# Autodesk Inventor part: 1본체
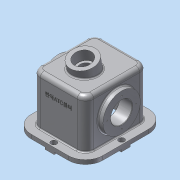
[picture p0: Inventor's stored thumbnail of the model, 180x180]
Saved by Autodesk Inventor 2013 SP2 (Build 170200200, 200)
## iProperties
Created: 2014-11
Part Number: 1본체
Material: 알루미늄 6061
Document SubType Name: Modeling
Designer: dgall
Density: 2.71 g/cm^3
Mass: 2882.15 g
Surface Area: 2079.16 cm^2
Volume: 1063.52 cm^3
Author: dgall
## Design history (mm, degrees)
sketch "스케치1"
  geometry: L1 (-76, 59)-(76, 59); L2 (76, 59)-(76, -59); L3 (76, -59)-(-76, -59); L4 (-76, -59)-(-76, 59); 3 further points
  constraints: 8 end point, 2 midpoint, 2 parallel, 1 horizontal, 1 horizontal alignment, 1 perpendicular, 1 vertical alignment
  dimensions: "d0" = 152 distance of L1.start L1.end; "d2" = 118 distance of L1.end L2.end
extrude "돌출1" new body sketch "스케치1" stored distance "d3" = 130; taper "d4" = 0 deg
feature "쉘1" dims "d5" = 10
sketch "스케치2"
  geometry: L1 (142, -10)-(142, -120) reference; L2 (142, -120)-(10, -120) reference; L3 (10, -120)-(10, -10) reference; L4 (10, -10)-(142, -10) reference; L5 (174, -152)-(-22, -152); L6 (-22, -152)-(-22, 22); L7 (-22, 22)-(174, 22); L8 (174, 22)-(174, -152); 3 further points
  constraints: 8 end point, 2 midpoint, 2 parallel, 1 horizontal, 1 horizontal alignment, 1 perpendicular, 1 vertical alignment
  dimensions: "d6" = 196 distance of L5.start L5.end; "d8" = 174 distance of L5.end L6.end
extrude "돌출2" join sketch "스케치2" distance "d9" = 10; taper "d10" = 0 deg
sketch "스케치3"
  geometry: L1 (152, -128)-(-22, -128) reference; 2 further points
  constraints: 1 vertical alignment, 1 other
  dimensions: "d11" = 92 distance from line of point (65, -36) L1
feature "엠보싱1" sketch "스케치3" dims "d6" = 196, "d8" = 174, "d12" = 1, "d13" = 0
sketch "스케치4"
  geometry: L1 (-66, -69)-(66, -69) reference; C1 r 45.5 at (0, -1); 1 further point
  constraints: 1 centre point, 1 vertical alignment
  dimensions: "d15" = 91 diameter of C1; "d57" = 68 distance from line of C1.centre L1
extrude "돌출3" join sketch "스케치4" distance "d16" = 12; taper "d17" = 0 deg
sketch "스케치5"
  geometry: C1 r 45.5 at (0, 0) reference; 2 further points
  constraints: 1 vertical alignment
  dimensions: "d18" = 35 distance of point (0, 35) C1.centre
hole "구멍1" sketch "스케치5" at (0, 35) diameter "d19" = 3.242; stored, may be unused: countersink angle "d23" = 90 deg, drill point angle "d25" = 118 deg; dims "d20" = 13, "d21" = 4, "d22" = 2, "d24" = 16
sketch "스케치6"
  geometry: L1 (174, -152)-(174, 22) reference; L2 (-22, 22)-(-22, -152) reference; L3 (174, -54)-(154, -54); L4 (154, -54)-(154, -76); L5 (154, -76)-(174, -76); L6 (174, 22)-(-22, 22) reference; L7 (87, 22)-(87, 2); L8 (87, 2)-(65, 2); L9 (65, 2)-(65, 22); 3 further points
  constraints: 12 end point, 5 perpendicular, 4 point on line, 2 midpoint, 1 horizontal alignment, 1 vertical, 1 vertical alignment
  dimensions: "d29" = 22 distance between parallel lines of L5 L3; "d31" = 20 distance of L4.end L5.end; "d42" = 22 distance between parallel lines of L9 L7; "d43" = 20 distance between parallel lines of L8 L6
extrude "돌출4" join sketch "스케치6" distance "d32" = 5; taper "d33" = 0 deg
sketch "스케치7"
  geometry: L1 (174, -22)-(174, 152) reference; 2 further points
  constraints: 1 horizontal alignment
  dimensions: "d34" = 10 distance from line of point (164, 65) L1
hole "구멍2" sketch "스케치7" at (164, 65) diameter "d35" = 9; stored, may be unused: countersink angle "d39" = 90 deg, drill point angle "d41" = 0 deg; dims "d36" = 13, "d37" = 14, "d38" = 8.6, "d40" = 32
sketch "스케치8"
  geometry: L1 (174, 22)-(-22, 22) reference; L2 (142, -10)-(142, -120) reference; L3 (87, 22)-(87, 2); L4 (87, 2)-(65, 2); L5 (65, 2)-(65, 22); 2 further points
  constraints: 6 end point, 2 perpendicular, 2 point on line, 1 midpoint, 1 parallel, 1 vertical alignment
  dimensions: "d44" = 22 distance between parallel lines of L5 L3; "d46" = 20 distance between parallel lines of L4 L1
extrude "돌출5" join sketch "스케치8" distance "d47" = 5; taper "d48" = 0 deg
sketch "스케치9"
  geometry: L1 (-22, -22)-(174, -22) reference; 2 further points
  constraints: 1 vertical alignment
  dimensions: "d49" = 10 distance from line of point (76, -12) L1
hole "구멍3" sketch "스케치9" at (76, -12) diameter "d50" = 9; stored, may be unused: countersink angle "d54" = 90 deg, drill point angle "d56" = 0 deg; dims "d51" = 13, "d52" = 14, "d53" = 8.6, "d55" = 32
sketch "스케치10"
  geometry: L1 (44.5, 77)-(-46.5, 77) reference; L2 (49, 55)-(-69, 55) reference; L3 (-1, 55)-(-1, 45); L4 (-1, 45)-(34.5, 45); L5 (34.5, 45)-(44.5, 55); 2 further points
  constraints: 6 end point, 2 point on line, 1 midpoint, 1 parallel, 1 perpendicular, 1 vertical alignment
  dimensions: "d58" = 91 diameter of L5.end L3; "d60" = 71 diameter of L4.end L3; "d61" = 32 distance between parallel lines of L4 L1
revolve "회전1" sketch "스케치10" stored, may be unused: angle "d62" = 90 deg
hole "구멍4" diameter "d65" = 52; stored, may be unused: countersink angle "d69" = 90 deg, drill point angle "d71" = 0 deg; dims "d66" = 13, "d67" = 14, "d68" = 8.6, "d70" = 32, "d72" = 10, "d73" = 10
sketch "스케치11"
  geometry: L1 (-76, 59)-(76, 59) reference; L2 (0, -1)-(76, -1); L3 (0, -1)-(17.88, 83.121); C1 r 45.5 at (0, -1) reference; 1 further point
  constraints: 4 end point, 1 parallel
  dimensions: "d100" = 86 distance of L3.end L2.start; "d101" = 78 deg angle of L2 L3
node "작업점1"
node "작업 평면1"
sketch "스케치12"
  geometry: C1 r 31 at (0.208, 0); C2 r 21 at (0.208, 0); C3 r 15 at (0.208, 0); 1 further point
  constraints: 3 centre point, 3 coincident
  dimensions: "d77" = 62 diameter of C1; "d82" = 42 diameter of C2; "d83" = 30 diameter of C3
extrude "돌출6" join sketch "스케치12" stored distance "d79" = 20; taper "d80" = 0 deg
extrude "돌출7" cut sketch "스케치12" distance "d84" = 25; taper "d85" = 0 deg
extrude "돌출8" cut sketch "스케치12" stored distance "d86" = 25; taper "d87" = 0 deg
chamfer "모따기1" distance "d88" = 1; stored, may be unused: second distance "d89" = 2, angle "d90" = 45 deg
fillet "모깎기1" dims "d91" = 20
fillet "모깎기2" dims "d92" = 10
fillet "모깎기3" dims "d93" = 10
fillet "모깎기4" dims "d94" = 3
fillet "모깎기5" dims "d95" = 3
fillet "모깎기6" dims "d96" = 3
fillet "모깎기7" dims "d97" = 42
fillet "모깎기8" dims "d98" = 0.3
fillet "모깎기9" dims "d99" = 3
node "솔리드1"
pattern_circular "원형 패턴1" dims angle "d27" = 360 deg
mirror "대칭1"
mirror "대칭2"
mirror "대칭3"
mirror "대칭4"
